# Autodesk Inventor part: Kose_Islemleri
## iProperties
Shininess: 64.0
Length Units: 11269
Angle Units: 11279
Time Units: 11290
Mass Units: 11283
Length Display Precision: 3
Angle Display Precision: 2
Compacted: True
Part Number: Kose_Islemleri
Document SubType Name: Sheet Metal
Created: 2003-09
Material: Stainless Steel, 440C
Designer: Ronald Myers
Manufacturer: Standard
Standards Organization: Custom
Density: 1 g/cm^3
Sheet Metal Rule: 1.0 mm Stainless
Density: 0.0
Volumn: 0.0
Area: 0.0
PropertySet Name: Model Information
Control State: 0
Master: False
Checked Out: False
Author: Ronald Myers
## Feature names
1. Bend4
2. Bend5
3. Plate1
4. Plate3
5. Bend2
6. Plate4
7. Bend3
8. Plate5
9. Bend6
10. Plate6
11. Bend7
12. Plate7
13. Bend8
14. Plate8
15. Bend9
